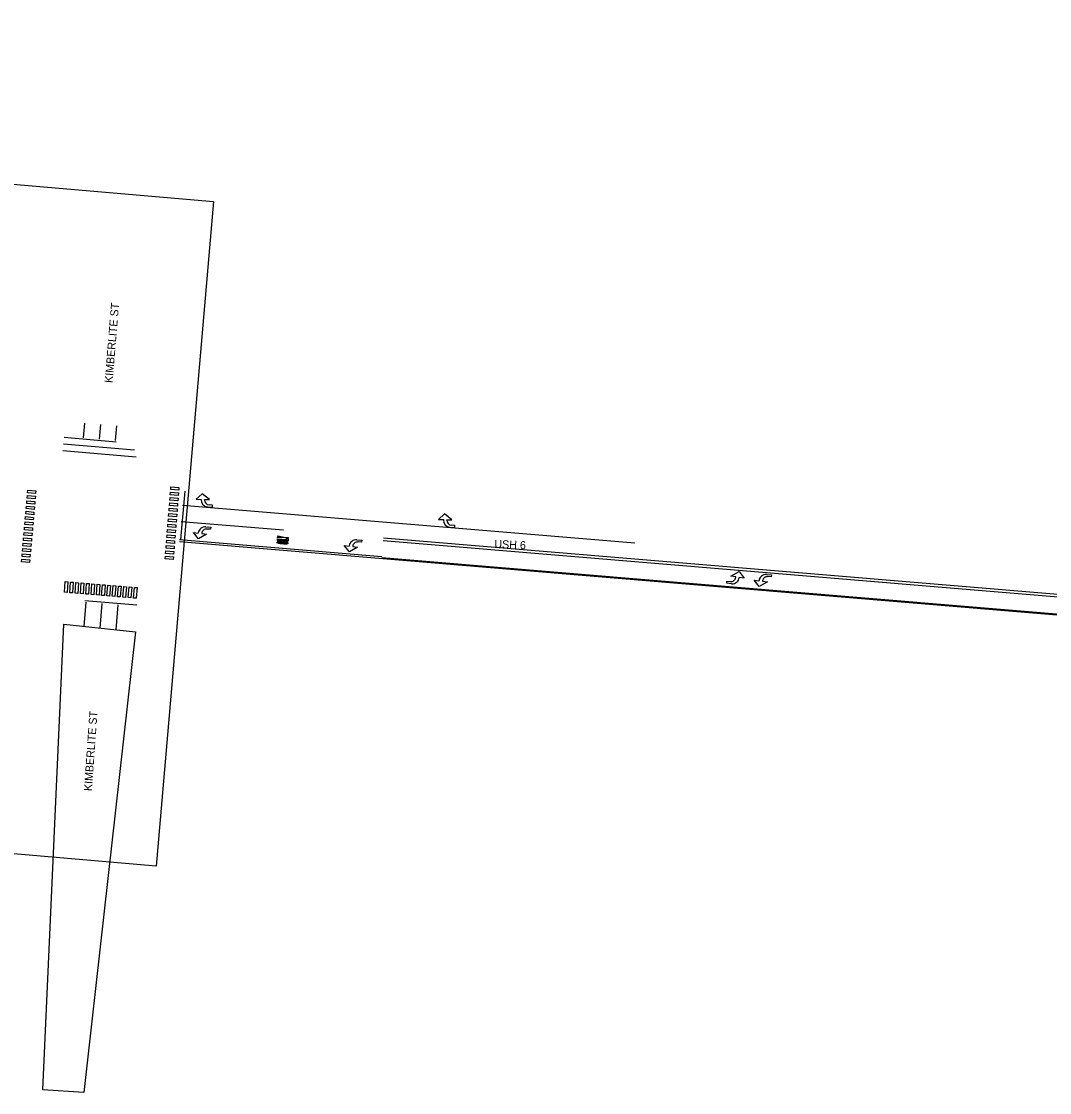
# Model space of a CAD drawing. Extents: x 20499978 to 20505524, y 7953342 to 7954320.
# Drawn here: x 20503170 to 20503940, y 7953342 to 7954145 of the extents above; entities that cross this region are included whole.
import ezdxf

# ---------------------------------------------------------------- set-up
doc = ezdxf.new("R2010")
doc.units = 0
for name, color, linetype in [('EdgePaved', 7, 'Continuous'), ('Entrance', 7, 'Continuous'), ('Stage 2A - Existing Pavement', 7, 'Continuous'), ('Text', 7, 'Continuous'), ('trf_Cells1', 7, 'Continuous'), ('UtilitiesBelowGround', 7, 'Continuous')]:
    doc.layers.add(name, color=color, linetype=linetype)

msp = doc.modelspace()

# ---------------------------------------------------------------- linework, layer by layer
at = {"layer": 'EdgePaved'}
for p, q in [((20503217.07, 7953843.86), (20503216.15, 7953832.89)), ((20503229.03, 7953842.86), (20503228.11, 7953831.89)), ((20503240.97, 7953841.87), (20503240.05, 7953830.88)), ((20503240.79, 7953829.81), (20503201.74, 7953833.1)), ((20503254.59, 7953823.63), (20503201.32, 7953828.12)), ((20503255.72, 7953818.52), (20503200.9, 7953823.14)), ((20503174.46, 7953791.83), (20503174.64, 7953793.82)), ((20503174.64, 7953793.82), (20503180.61, 7953793.29)), ((20503180.61, 7953793.29), (20503180.44, 7953791.3)), ((20503281.67, 7953794.17), (20503281.83, 7953796.16)), ((20503287.65, 7953793.69), (20503281.67, 7953794.17)), ((20503281.83, 7953796.16), (20503287.81, 7953795.68)), ((20503287.81, 7953795.68), (20503287.65, 7953793.69)), ((20503289.33, 7953756.73), (20503292.36, 7953793.09)), ((20503173.75, 7953783.86), (20503173.93, 7953785.86)), ((20503173.93, 7953785.86), (20503179.91, 7953785.33)), ((20503174.11, 7953787.85), (20503174.28, 7953789.84)), ((20503180.08, 7953787.32), (20503174.11, 7953787.85)), ((20503174.28, 7953789.84), (20503180.26, 7953789.31)), ((20503180.44, 7953791.3), (20503174.46, 7953791.83)), ((20503179.91, 7953785.33), (20503179.73, 7953783.33)), ((20503180.26, 7953789.31), (20503180.08, 7953787.32)), ((20503281.03, 7953786.2), (20503281.19, 7953788.19)), ((20503287.01, 7953785.71), (20503281.03, 7953786.2)), ((20503281.19, 7953788.19), (20503287.17, 7953787.71)), ((20503281.35, 7953790.18), (20503281.51, 7953792.18)), ((20503287.33, 7953789.7), (20503281.35, 7953790.18)), ((20503281.51, 7953792.18), (20503287.49, 7953791.7)), ((20503287.17, 7953787.71), (20503287.01, 7953785.71)), ((20503287.49, 7953791.7), (20503287.33, 7953789.7)), ((20503173.05, 7953775.89), (20503173.22, 7953777.89)), ((20503173.22, 7953777.89), (20503179.2, 7953777.36)), ((20503173.4, 7953779.88), (20503173.58, 7953781.87)), ((20503179.38, 7953779.35), (20503173.4, 7953779.88)), ((20503173.58, 7953781.87), (20503179.55, 7953781.34)), ((20503179.73, 7953783.33), (20503173.75, 7953783.86)), ((20503179.2, 7953777.36), (20503179.02, 7953775.37)), ((20503179.55, 7953781.34), (20503179.38, 7953779.35)), ((20503280.39, 7953778.22), (20503280.55, 7953780.21)), ((20503286.37, 7953777.74), (20503280.39, 7953778.22)), ((20503280.55, 7953780.21), (20503286.53, 7953779.73)), ((20503280.71, 7953782.21), (20503280.87, 7953784.2)), ((20503286.69, 7953781.73), (20503280.71, 7953782.21)), ((20503280.87, 7953784.2), (20503286.85, 7953783.72)), ((20503286.53, 7953779.73), (20503286.37, 7953777.74)), ((20503286.85, 7953783.72), (20503286.69, 7953781.73)), ((20503629.36, 7953754.02), (20503290.46, 7953782.3)), ((20503172.34, 7953767.93), (20503172.52, 7953769.92)), ((20503172.52, 7953769.92), (20503178.5, 7953769.39)), ((20503172.7, 7953771.91), (20503172.87, 7953773.9)), ((20503178.67, 7953771.38), (20503172.7, 7953771.91)), ((20503172.87, 7953773.9), (20503178.85, 7953773.37)), ((20503179.02, 7953775.37), (20503173.05, 7953775.89)), ((20503178.5, 7953769.39), (20503178.32, 7953767.4)), ((20503178.85, 7953773.37), (20503178.67, 7953771.38)), ((20503279.75, 7953770.25), (20503279.91, 7953772.24)), ((20503285.73, 7953769.77), (20503279.75, 7953770.25)), ((20503279.91, 7953772.24), (20503285.89, 7953771.76)), ((20503280.07, 7953774.23), (20503280.23, 7953776.23)), ((20503286.05, 7953773.75), (20503280.07, 7953774.23)), ((20503280.23, 7953776.23), (20503286.21, 7953775.75)), ((20503285.89, 7953771.76), (20503285.73, 7953769.77)), ((20503286.21, 7953775.75), (20503286.05, 7953773.75)), ((20503289.46, 7953770.34), (20503366.27, 7953763.93)), ((20503171.64, 7953759.96), (20503171.81, 7953761.95)), ((20503171.81, 7953761.95), (20503177.79, 7953761.42)), ((20503171.99, 7953763.94), (20503172.17, 7953765.93)), ((20503177.97, 7953763.41), (20503171.99, 7953763.94)), ((20503172.17, 7953765.93), (20503178.14, 7953765.4)), ((20503178.32, 7953767.4), (20503172.34, 7953767.93)), ((20503177.79, 7953761.42), (20503177.61, 7953759.43)), ((20503178.14, 7953765.4), (20503177.97, 7953763.41)), ((20503279.11, 7953762.27), (20503279.27, 7953764.27)), ((20503285.09, 7953761.79), (20503279.11, 7953762.27)), ((20503279.27, 7953764.27), (20503285.25, 7953763.79)), ((20503279.43, 7953766.26), (20503279.59, 7953768.25)), ((20503285.41, 7953765.78), (20503279.43, 7953766.26)), ((20503279.59, 7953768.25), (20503285.57, 7953767.77)), ((20503285.25, 7953763.79), (20503285.09, 7953761.79)), ((20503285.57, 7953767.77), (20503285.41, 7953765.78)), ((20503170.93, 7953751.99), (20503171.11, 7953753.98)), ((20503171.11, 7953753.98), (20503177.08, 7953753.45)), ((20503171.28, 7953755.97), (20503171.46, 7953757.96)), ((20503177.26, 7953755.44), (20503171.28, 7953755.97)), ((20503171.46, 7953757.96), (20503177.44, 7953757.44)), ((20503177.61, 7953759.43), (20503171.64, 7953759.96)), ((20503177.08, 7953753.45), (20503176.91, 7953751.46)), ((20503177.44, 7953757.44), (20503177.26, 7953755.44)), ((20503278.47, 7953754.3), (20503278.63, 7953756.29)), ((20503284.45, 7953753.82), (20503278.47, 7953754.3)), ((20503278.63, 7953756.29), (20503284.61, 7953755.81)), ((20503278.79, 7953758.29), (20503278.95, 7953760.28)), ((20503284.77, 7953757.8), (20503278.79, 7953758.29)), ((20503278.95, 7953760.28), (20503284.93, 7953759.8)), ((20503284.61, 7953755.81), (20503284.45, 7953753.82)), ((20503284.93, 7953759.8), (20503284.77, 7953757.8)), ((20503439.81, 7953743.75), (20503288.29, 7953756.39)), ((20504365.67, 7953680.54), (20503441.01, 7953757.69)), ((20503170.23, 7953744.02), (20503170.4, 7953746.01)), ((20503170.4, 7953746.01), (20503176.38, 7953745.48)), ((20503170.58, 7953748), (20503170.75, 7953750)), ((20503176.55, 7953747.47), (20503170.58, 7953748)), ((20503170.75, 7953750), (20503176.73, 7953749.47)), ((20503176.91, 7953751.46), (20503170.93, 7953751.99)), ((20503176.38, 7953745.48), (20503176.2, 7953743.49)), ((20503176.73, 7953749.47), (20503176.55, 7953747.47)), ((20503277.82, 7953746.32), (20503277.98, 7953748.32)), ((20503283.81, 7953745.84), (20503277.82, 7953746.32)), ((20503277.98, 7953748.32), (20503283.97, 7953747.84)), ((20503278.15, 7953750.31), (20503278.31, 7953752.3)), ((20503284.13, 7953749.83), (20503278.15, 7953750.31)), ((20503278.31, 7953752.3), (20503284.29, 7953751.82)), ((20503283.97, 7953747.84), (20503283.81, 7953745.84)), ((20503284.29, 7953751.82), (20503284.13, 7953749.83)), ((20503169.87, 7953740.03), (20503170.05, 7953742.03)), ((20503175.85, 7953739.51), (20503169.87, 7953740.03)), ((20503170.05, 7953742.03), (20503176.03, 7953741.5)), ((20503176.2, 7953743.49), (20503170.23, 7953744.02)), ((20503176.03, 7953741.5), (20503175.85, 7953739.51)), ((20503277.5, 7953742.34), (20503277.66, 7953744.33)), ((20503283.48, 7953741.86), (20503277.5, 7953742.34)), ((20503277.66, 7953744.33), (20503283.64, 7953743.85)), ((20503283.64, 7953743.85), (20503283.48, 7953741.86)), ((20503202.01, 7953717.19), (20503202.68, 7953725.16)), ((20503202.68, 7953725.16), (20503204.67, 7953724.99)), ((20503204.67, 7953724.99), (20503204, 7953717.02)), ((20503206, 7953716.85), (20503206.66, 7953724.82)), ((20503206.66, 7953724.82), (20503208.66, 7953724.66)), ((20503208.66, 7953724.66), (20503207.99, 7953716.69)), ((20503209.98, 7953716.52), (20503210.65, 7953724.49)), ((20503210.65, 7953724.49), (20503212.64, 7953724.32)), ((20503212.64, 7953724.32), (20503211.98, 7953716.35)), ((20503213.97, 7953716.19), (20503214.64, 7953724.16)), ((20503214.64, 7953724.16), (20503216.63, 7953723.99)), ((20503216.63, 7953723.99), (20503215.96, 7953716.02)), ((20503217.96, 7953715.85), (20503218.62, 7953723.82)), ((20503218.62, 7953723.82), (20503220.62, 7953723.66)), ((20503220.62, 7953723.66), (20503219.95, 7953715.69)), ((20503221.94, 7953715.52), (20503222.61, 7953723.49)), ((20503222.61, 7953723.49), (20503224.6, 7953723.33)), ((20503224.6, 7953723.33), (20503223.94, 7953715.35)), ((20503225.93, 7953715.19), (20503226.59, 7953723.16)), ((20503226.59, 7953723.16), (20503228.59, 7953722.99)), ((20503228.59, 7953722.99), (20503227.92, 7953715.02)), ((20503229.91, 7953714.85), (20503230.58, 7953722.83)), ((20503230.58, 7953722.83), (20503232.57, 7953722.66)), ((20503232.57, 7953722.66), (20503231.91, 7953714.69)), ((20503233.9, 7953714.52), (20503234.57, 7953722.49)), ((20503234.57, 7953722.49), (20503236.56, 7953722.33)), ((20503236.56, 7953722.33), (20503235.89, 7953714.35)), ((20503237.89, 7953714.19), (20503238.55, 7953722.16)), ((20503238.55, 7953722.16), (20503240.55, 7953721.99)), ((20503240.55, 7953721.99), (20503239.88, 7953714.02)), ((20503241.87, 7953713.85), (20503242.54, 7953721.83)), ((20503242.54, 7953721.83), (20503244.53, 7953721.66)), ((20503244.53, 7953721.66), (20503243.87, 7953713.69)), ((20503245.86, 7953713.52), (20503246.52, 7953721.49)), ((20503246.52, 7953721.49), (20503248.52, 7953721.33)), ((20503248.52, 7953721.33), (20503247.85, 7953713.35)), ((20503249.84, 7953713.19), (20503250.51, 7953721.16)), ((20503250.51, 7953721.16), (20503252.5, 7953720.99)), ((20503252.5, 7953720.99), (20503251.84, 7953713.02)), ((20503253.83, 7953712.85), (20503254.5, 7953720.83)), ((20503254.5, 7953720.83), (20503256.49, 7953720.66)), ((20503256.49, 7953720.66), (20503255.82, 7953712.69)), ((20503204, 7953717.02), (20503202.01, 7953717.19)), ((20503207.99, 7953716.69), (20503206, 7953716.85)), ((20503211.98, 7953716.35), (20503209.98, 7953716.52)), ((20503215.96, 7953716.02), (20503213.97, 7953716.19)), ((20503219.95, 7953715.69), (20503217.96, 7953715.85)), ((20503223.94, 7953715.35), (20503221.94, 7953715.52)), ((20503227.92, 7953715.02), (20503225.93, 7953715.19)), ((20503231.91, 7953714.69), (20503229.91, 7953714.85)), ((20503235.89, 7953714.35), (20503233.9, 7953714.52)), ((20503239.88, 7953714.02), (20503237.89, 7953714.19)), ((20503243.87, 7953713.69), (20503241.87, 7953713.85)), ((20503247.85, 7953713.35), (20503245.86, 7953713.52)), ((20503251.84, 7953713.02), (20503249.84, 7953713.19)), ((20503255.82, 7953712.69), (20503253.83, 7953712.85)), ((20503218.1, 7953709.82), (20503216.58, 7953691.64)), ((20503256.21, 7953707.64), (20503217.35, 7953710.88)), ((20503230.13, 7953708.81), (20503228.58, 7953690.34)), ((20503242.11, 7953707.81), (20503240.54, 7953689.05))]:
    msp.add_line(p, q, dxfattribs=at)
for points in [[(20504428.95, 7953659.7), (20504247.31, 7953674.86), (20503288.17, 7953754.9)], [(20504430.08, 7953673.24), (20504365.51, 7953678.63), (20503440.85, 7953755.78)], [(20504429.02, 7953660.45), (20504247.38, 7953675.6), (20503439.75, 7953743)]]:
    msp.add_lwpolyline(points, dxfattribs=at)
at = {"layer": 'Entrance'}
for p, q in [((20503304.42, 7953786.83), (20503304.4, 7953786.64)), ((20503307.02, 7953786.42), (20503307.05, 7953786.74)), ((20503485.96, 7953771.65), (20503485.94, 7953771.47)), ((20503488.56, 7953771.25), (20503488.59, 7953771.57)), ((20503302.29, 7953761.51), (20503302.31, 7953761.7)), ((20503304.92, 7953761.47), (20503304.9, 7953761.15)), ((20503415.39, 7953751.78), (20503415.41, 7953751.96)), ((20503418.03, 7953751.73), (20503418, 7953751.42)), ((20503705, 7953728.36), (20503705.03, 7953728.68)), ((20503707.63, 7953728.32), (20503707.62, 7953728.14)), ((20503722.45, 7953725.79), (20503722.47, 7953725.97)), ((20503725.09, 7953725.74), (20503725.06, 7953725.43))]:
    msp.add_line(p, q, dxfattribs=at)
for points in [[(20503305.3, 7953791.07), (20503300.74, 7953786.95), (20503304.42, 7953786.83)], [(20503305.3, 7953791.07), (20503300.74, 7953786.95), (20503304.42, 7953786.83)], [(20503304.42, 7953786.83), (20503304.4, 7953786.64)], [(20503307.05, 7953786.74), (20503310.73, 7953786.62), (20503305.3, 7953791.07)], [(20503307.05, 7953786.74), (20503310.73, 7953786.62), (20503305.3, 7953791.07)], [(20503307.02, 7953786.42), (20503307.05, 7953786.74)], [(20503309.23, 7953781.24), (20503312.9, 7953780.94), (20503313.02, 7953782.43), (20503310.4, 7953782.64)], [(20503309.23, 7953781.24), (20503312.9, 7953780.94), (20503313.02, 7953782.43), (20503310.4, 7953782.64)], [(20503486.84, 7953775.89), (20503482.28, 7953771.78), (20503485.96, 7953771.65)], [(20503486.84, 7953775.89), (20503482.28, 7953771.78), (20503485.96, 7953771.65)], [(20503485.96, 7953771.65), (20503485.94, 7953771.47)], [(20503488.59, 7953771.57), (20503492.27, 7953771.44), (20503486.84, 7953775.89)], [(20503488.59, 7953771.57), (20503492.27, 7953771.44), (20503486.84, 7953775.89)], [(20503488.56, 7953771.25), (20503488.59, 7953771.57)], [(20503302.44, 7953757.18), (20503298.64, 7953762.01), (20503302.29, 7953761.51)], [(20503302.44, 7953757.18), (20503298.64, 7953762.01), (20503302.29, 7953761.51)], [(20503302.29, 7953761.51), (20503302.31, 7953761.7)], [(20503304.9, 7953761.15), (20503308.55, 7953760.65), (20503302.44, 7953757.18)], [(20503304.9, 7953761.15), (20503308.55, 7953760.65), (20503302.44, 7953757.18)], [(20503304.92, 7953761.47), (20503304.9, 7953761.15)], [(20503307.97, 7953766.2), (20503311.64, 7953765.88), (20503311.51, 7953764.39), (20503308.89, 7953764.62)], [(20503307.97, 7953766.2), (20503311.64, 7953765.88), (20503311.51, 7953764.39), (20503308.89, 7953764.62)], [(20503490.77, 7953766.07), (20503494.43, 7953765.77), (20503494.56, 7953767.25), (20503491.94, 7953767.47)], [(20503490.77, 7953766.07), (20503494.43, 7953765.77), (20503494.56, 7953767.25), (20503491.94, 7953767.47)], [(20503421.08, 7953756.47), (20503424.74, 7953756.15), (20503424.61, 7953754.66), (20503422, 7953754.89)], [(20503421.08, 7953756.47), (20503424.74, 7953756.15), (20503424.61, 7953754.66), (20503422, 7953754.89)], [(20503415.54, 7953747.45), (20503411.74, 7953752.28), (20503415.39, 7953751.78)], [(20503415.54, 7953747.45), (20503411.74, 7953752.28), (20503415.39, 7953751.78)], [(20503415.39, 7953751.78), (20503415.41, 7953751.96)], [(20503418, 7953751.42), (20503421.65, 7953750.92), (20503415.54, 7953747.45)], [(20503418, 7953751.42), (20503421.65, 7953750.92), (20503415.54, 7953747.45)], [(20503418.03, 7953751.73), (20503418, 7953751.42)], [(20503705.03, 7953728.68), (20503701.38, 7953729.18), (20503707.48, 7953732.65)], [(20503705.03, 7953728.68), (20503701.38, 7953729.18), (20503707.48, 7953732.65)], [(20503705, 7953728.36), (20503705.03, 7953728.68)], [(20503707.48, 7953732.65), (20503711.28, 7953727.82), (20503707.63, 7953728.32)], [(20503707.48, 7953732.65), (20503711.28, 7953727.82), (20503707.63, 7953728.32)], [(20503728.14, 7953730.48), (20503731.81, 7953730.16), (20503731.68, 7953728.67), (20503729.06, 7953728.9)], [(20503728.14, 7953730.48), (20503731.81, 7953730.16), (20503731.68, 7953728.67), (20503729.06, 7953728.9)], [(20503701.95, 7953723.63), (20503698.28, 7953723.95), (20503698.41, 7953725.44), (20503701.03, 7953725.21)], [(20503701.95, 7953723.63), (20503698.28, 7953723.95), (20503698.41, 7953725.44), (20503701.03, 7953725.21)], [(20503707.63, 7953728.32), (20503707.62, 7953728.14)], [(20503722.61, 7953721.46), (20503718.8, 7953726.29), (20503722.45, 7953725.79)], [(20503722.61, 7953721.46), (20503718.8, 7953726.29), (20503722.45, 7953725.79)], [(20503722.45, 7953725.79), (20503722.47, 7953725.97)], [(20503725.06, 7953725.43), (20503728.71, 7953724.93), (20503722.61, 7953721.46)], [(20503725.06, 7953725.43), (20503728.71, 7953724.93), (20503722.61, 7953721.46)], [(20503725.09, 7953725.74), (20503725.06, 7953725.43)]]:
    msp.add_lwpolyline(points, dxfattribs=at)
for centre, major_axis, start_param, end_param in [((20503309.64, 7953786.21), (5.24, -0.44), 3.141593, 4.712389), ((20503309.64, 7953786.21), (5.24, -0.44), 3.141593, 4.712389), ((20503310.69, 7953786.12), (3.67, -0.31), 3.141593, 4.712389), ((20503310.69, 7953786.12), (3.67, -0.31), 3.141593, 4.712389), ((20503491.18, 7953771.03), (5.24, -0.44), 3.141593, 4.712389), ((20503491.18, 7953771.03), (5.24, -0.44), 3.141593, 4.712389), ((20503492.23, 7953770.95), (3.67, -0.31), 3.141593, 4.712389), ((20503492.23, 7953770.95), (3.67, -0.31), 3.141593, 4.712389), ((20503307.54, 7953761.24), (5.24, -0.46), 1.570796, 3.141593), ((20503307.54, 7953761.24), (5.24, -0.46), 1.570796, 3.141593), ((20503308.59, 7953761.15), (3.67, -0.32), 1.570796, 3.141593), ((20503308.59, 7953761.15), (3.67, -0.32), 1.570796, 3.141593), ((20503420.65, 7953751.5), (5.24, -0.46), 1.570796, 3.141593), ((20503420.65, 7953751.5), (5.24, -0.46), 1.570796, 3.141593), ((20503421.69, 7953751.41), (3.67, -0.32), 1.570796, 3.141593), ((20503421.69, 7953751.41), (3.67, -0.32), 1.570796, 3.141593), ((20503727.71, 7953725.51), (5.24, -0.46), 1.570796, 3.141593), ((20503727.71, 7953725.51), (5.24, -0.46), 1.570796, 3.141593), ((20503728.75, 7953725.42), (3.67, -0.32), 1.570796, 3.141593), ((20503728.75, 7953725.42), (3.67, -0.32), 1.570796, 3.141593), ((20503701.33, 7953728.68), (-3.67, 0.32), 1.570796, 3.141593), ((20503701.33, 7953728.68), (-3.67, 0.32), 1.570796, 3.141593), ((20503702.38, 7953728.59), (-5.24, 0.46), 1.570796, 3.141593), ((20503702.38, 7953728.59), (-5.24, 0.46), 1.570796, 3.141593)]:
    msp.add_ellipse(centre, major_axis=major_axis, ratio=0.9474, start_param=start_param, end_param=end_param, dxfattribs=at)
at = {"layer": 'Stage 2A - Existing Pavement'}
msp.add_lwpolyline([(20503201.45, 7953693.28), (20503255.15, 7953687.47), (20503216.63, 7953342.16), (20503185.81, 7953344.24)], close=True, dxfattribs=at)
at = {"layer": 'Text'}
msp.add_lwpolyline([(20501752.19, 7954145.12), (20503313.82, 7954010.01), (20503270.73, 7953511.87), (20501709.09, 7953646.98)], close=True, dxfattribs=at)
at = {"layer": 'trf_Cells1'}
for p, q in [((20503366.18, 7953753.42), (20503364.58, 7953753.55)), ((20503364.61, 7953753.87), (20503366.2, 7953753.74)), ((20503366.26, 7953754.37), (20503364.66, 7953754.51)), ((20503364.69, 7953754.83), (20503366.28, 7953754.69))]:
    msp.add_line(p, q, dxfattribs=at)
for points in [[(20503369.5, 7953754.75), (20503361.53, 7953755.42), (20503361.55, 7953755.73), (20503366.71, 7953755.95), (20503361.61, 7953756.37), (20503361.63, 7953756.69), (20503369.6, 7953756.03), (20503369.58, 7953755.71), (20503364.42, 7953755.49), (20503369.52, 7953755.07)], [(20503369.63, 7953756.34), (20503361.66, 7953757.01), (20503361.69, 7953757.33), (20503368.38, 7953756.77), (20503368.46, 7953757.73), (20503369.74, 7953757.62)], [(20503361.75, 7953758.13), (20503361.78, 7953758.45), (20503364.99, 7953758.5), (20503361.83, 7953759.08), (20503361.86, 7953759.4), (20503366.6, 7953758.52), (20503369.79, 7953758.26), (20503369.76, 7953757.94), (20503366.58, 7953758.21)]]:
    msp.add_lwpolyline(points, close=True, dxfattribs=at)
for points in [[(20503364.58, 7953753.55), (20503364.38, 7953753.57), (20503364.09, 7953753.6), (20503363.91, 7953753.62), (20503363.7, 7953753.64), (20503363.56, 7953753.66), (20503363.39, 7953753.69), (20503363.26, 7953753.71), (20503363.1, 7953753.73), (20503362.9, 7953753.76), (20503362.8, 7953753.78), (20503362.71, 7953753.8), (20503362.58, 7953753.83), (20503362.43, 7953753.86), (20503362.3, 7953753.89), (20503362.16, 7953753.93), (20503362.04, 7953753.97), (20503361.92, 7953754.01), (20503361.77, 7953754.07), (20503361.64, 7953754.13), (20503361.55, 7953754.19), (20503361.5, 7953754.25), (20503361.47, 7953754.31), (20503361.45, 7953754.35), (20503361.44, 7953754.4), (20503361.45, 7953754.45)], [(20503361.45, 7953754.45), (20503361.45, 7953754.51), (20503361.47, 7953754.55), (20503361.49, 7953754.6), (20503361.53, 7953754.64), (20503361.59, 7953754.69), (20503361.69, 7953754.74), (20503361.83, 7953754.78), (20503361.98, 7953754.81), (20503362.12, 7953754.84), (20503362.24, 7953754.85), (20503362.38, 7953754.87), (20503362.52, 7953754.88), (20503362.66, 7953754.88), (20503362.8, 7953754.89), (20503362.89, 7953754.89), (20503362.99, 7953754.89), (20503363.2, 7953754.89), (20503363.36, 7953754.89), (20503363.49, 7953754.89), (20503363.66, 7953754.89), (20503363.8, 7953754.88), (20503364.01, 7953754.87), (20503364.19, 7953754.86), (20503364.49, 7953754.84), (20503364.69, 7953754.83)], [(20503364.66, 7953754.51), (20503364.51, 7953754.52), (20503364.28, 7953754.53), (20503363.97, 7953754.54), (20503363.71, 7953754.55), (20503363.45, 7953754.56), (20503363.24, 7953754.55), (20503363.07, 7953754.53), (20503362.91, 7953754.5), (20503362.81, 7953754.47), (20503362.75, 7953754.42), (20503362.72, 7953754.35)], [(20503362.72, 7953754.35), (20503362.74, 7953754.27), (20503362.79, 7953754.21), (20503362.88, 7953754.16), (20503363.03, 7953754.11), (20503363.2, 7953754.06), (20503363.41, 7953754.02), (20503363.66, 7953753.98), (20503363.92, 7953753.95), (20503364.23, 7953753.91), (20503364.45, 7953753.89), (20503364.61, 7953753.87)], [(20503369.42, 7953753.79), (20503369.41, 7953753.74), (20503369.39, 7953753.69), (20503369.37, 7953753.65), (20503369.34, 7953753.6), (20503369.27, 7953753.55), (20503369.17, 7953753.51), (20503369.03, 7953753.46), (20503368.88, 7953753.43), (20503368.75, 7953753.41), (20503368.62, 7953753.39), (20503368.48, 7953753.38), (20503368.34, 7953753.36), (20503368.2, 7953753.36), (20503368.07, 7953753.35), (20503367.97, 7953753.35), (20503367.87, 7953753.35), (20503367.66, 7953753.35), (20503367.51, 7953753.35), (20503367.37, 7953753.35), (20503367.21, 7953753.36), (20503367.06, 7953753.36), (20503366.85, 7953753.37), (20503366.67, 7953753.38), (20503366.37, 7953753.4), (20503366.18, 7953753.42)], [(20503366.2, 7953753.74), (20503366.36, 7953753.73), (20503366.59, 7953753.71), (20503366.89, 7953753.7), (20503367.16, 7953753.69), (20503367.41, 7953753.69), (20503367.62, 7953753.69), (20503367.8, 7953753.71), (20503367.96, 7953753.74), (20503368.05, 7953753.77), (20503368.11, 7953753.82), (20503368.14, 7953753.9)], [(20503368.14, 7953753.9), (20503368.13, 7953753.98), (20503368.07, 7953754.03), (20503367.99, 7953754.08), (20503367.83, 7953754.13), (20503367.66, 7953754.18), (20503367.46, 7953754.22), (20503367.21, 7953754.26), (20503366.94, 7953754.3), (20503366.64, 7953754.33), (20503366.41, 7953754.36), (20503366.26, 7953754.37)], [(20503366.28, 7953754.69), (20503366.48, 7953754.67), (20503366.78, 7953754.65), (20503366.95, 7953754.62), (20503367.17, 7953754.6), (20503367.31, 7953754.58), (20503367.47, 7953754.56), (20503367.61, 7953754.54), (20503367.76, 7953754.51), (20503367.96, 7953754.48), (20503368.06, 7953754.46), (20503368.16, 7953754.44), (20503368.29, 7953754.42), (20503368.43, 7953754.39), (20503368.56, 7953754.35), (20503368.7, 7953754.31), (20503368.82, 7953754.28), (20503368.95, 7953754.23), (20503369.09, 7953754.17), (20503369.22, 7953754.11), (20503369.31, 7953754.05), (20503369.37, 7953753.99), (20503369.39, 7953753.94), (20503369.41, 7953753.89), (20503369.42, 7953753.84), (20503369.42, 7953753.79)]]:
    msp.add_spline(points, degree=3, dxfattribs=at)

# ---------------------------------------------------------------- texts
at = {"layer": 'UtilitiesBelowGround'}
for s, rotation, p in [('KIMBERLITE ST', 85.27579, (20503238.06, 7953873.93)), ('USH 6', 357.50172, (20503524.04, 7953750.48)), ('KIMBERLITE ST', 85.95271, (20503222.58, 7953567.98))]:
    msp.add_text(s, height=6, rotation=rotation, dxfattribs=at).set_placement(p)

doc.saveas('drawing.dxf')
